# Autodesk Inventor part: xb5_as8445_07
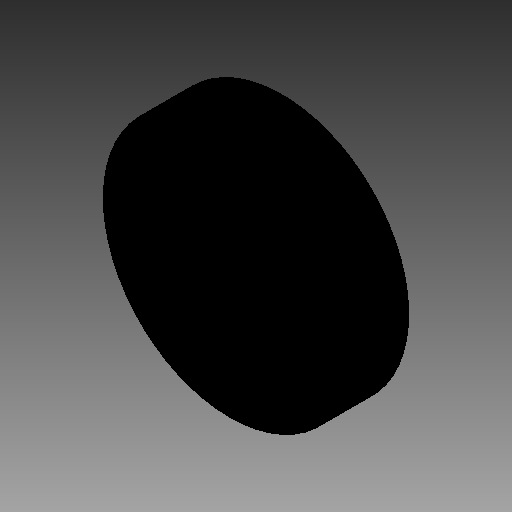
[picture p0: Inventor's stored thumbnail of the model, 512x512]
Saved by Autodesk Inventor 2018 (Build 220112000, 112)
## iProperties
Company: TraceParts S.A.
Created: 2018-04
Part Number: xb5_as8445_07
Checked By: TraceParts S.A.
Material: Generic
Catalog Web Link: www.traceparts.com
Document SubType Name: Modeling
Designer: TraceParts
Density: 1 g/cm^3
Appearance: Default
Author: TraceParts
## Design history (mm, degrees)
feature "xb5_as8445_07.ipt"
body "Solid1"
